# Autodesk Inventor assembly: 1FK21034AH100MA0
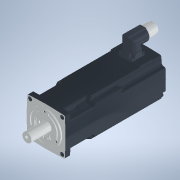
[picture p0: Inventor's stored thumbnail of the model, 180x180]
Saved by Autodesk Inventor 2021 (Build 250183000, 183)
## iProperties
Category: PARTsolutions
Created: 2026-06
Part Number: 1FK21034AH100MA0
Catalog Web Link: www.3dfindit.com
Description: 1FK21034AH100MA0-Servo synchronous motor
Document SubType Name: Assembly
Designer: psAdmin
Mass: 351.74 g
Surface Area: 934.015 cm^2
Volume: 351.74 cm^3
Density: 1 g/cm^3
Title: 1FK21034AH100MA0
Author: Cadenas PARTsolutions
Comments: Servo synchronous motor
PSOL_IDENT_0: {$CADENAS_DATA/23d-libs/siemens_ag/_cat_/39/97/1fk21034ah100ma0.prj},193 {STYP=ASS},{VTYP=3D},{NB=1F
PSOL_IDENT_1: K21034AH100MA0},{LINA=1FK21034AH100MA0},{NN=1FK21034AH100MA0},{DATE=19.08.2025 14:00:33},{GEOMDATE=3
PSOL_IDENT_2: 0.07.2025 02:02:21},{VERSION=},{LINEID=10},{WBVAR=},{WBNUMERIC=}  {NB=1FK21034AH100MA0},{LINA=1FK210
PSOL_IDENT_3: 34AH100MA0},{KT=DUMMY},{PREVIEW=../../../_pool_/d3/78/p_d211_xx_00934j.png},{DESCSHORT=SIMOTICS S-1F
PSOL_IDENT_4: K2 HD, SINAMICS S210 3AC 400V-480V, 1.01 Nm, 4500 rpm},{DESCLONG=SIMOTICS S-1FK2 HD servo motor M0=1
PSOL_IDENT_5: .27 Nm; PN = 0.48 kW at nN=4500 rpm (380-480 V); PN = 0.3 kW at nN=2500 rpm (200-240 V); with holdin
PSOL_IDENT_6: g brake; degree of protection IP64; cylindrical shaft D14 x 30 mm; absolute encoder 22-bit + 12-bit
PSOL_IDENT_7: multiturn (encoder AM22DQC); with OCC interface; plug size M17, rotatable; SIMOTICS S-1FK2 servomoto
PSOL_IDENT_8: rfor a wide range of uses in industrial environments. SIMOTICS S‑1FK2 servomotors are compact synchr
PSOL_IDENT_9: onous motors with a high dynamic performance that set themselves apart as a result of their high pow
PSOL_IDENT_10: er density, degree of protection and overload capability. The motors are available in two variants:
PSOL_IDENT_11: as High Dynamic variant (highest dynamic performance as a result of the low intrinsic moment of iner
PSOL_IDENT_12: tia for applications demanding a high dynamic performance with low moved masses) - and as Compact va
PSOL_IDENT_13: riant (precise and stable closed-loop control for medium up to large moved masses as a result of a m
PSOL_IDENT_14: edium intrinsic moment of inertia). SIMOTICSS‑1FK2 servomotors fully exploit their strengths in a sy
PSOL_IDENT_15: stem with the SINAMICSS210 frequency converter and simple connection using the one cable connection
PSOL_IDENT_16: (OCC). Advantages include the short control and positioning times, fast and precise correction of di
PSOL_IDENT_17: sturbing quantities as well as stable control with a high dynamic performance. The servo motors can
PSOL_IDENT_18: be configured to address a wide range of requirements. For example with and without holding brake, I
PSOL_IDENT_19: P64 or IP65 degree of protection, singleturn or multiturn absolute encoders - to name just a few. Fu
PSOL_IDENT_20: rther, the servomotors are available in different shaft heights extending from 20 to 100. A shaft se
PSOL_IDENT_21: aling ring is available to achieve an IP65 degree of protection and for subsequent mounting at the m
PSOL_IDENT_22: otor or as spare part. SIMOTICS - the optimum motor for each and every motion control application.},
PSOL_IDENT_23: {INTNO=195125454019},{SUPPLIERALTNO=1FK2103-4AH10-0MA0},{MANUID=1FK21034AH100MA0},{MANUNAME=Siemens}
PSOL_IDENT_24: ,{MANUTYPEDESC=SYNCHRONOUS MOTOR 1FK2 HD 1,27 NM},{AAU732=SIMOTICS},{AAO057=S-1FK2},{AAU734=SIMOTICS
PSOL_IDENT_25: S-1FK2 HD servo motor M0=1.27 Nm; PN = 0.48 kW at nN=4500 rpm (380-480 V); PN = 0.3 kW at nN=2500 r
PSOL_IDENT_26: pm (200-240 V); with holding brake; degree of protection IP64; cylindrical shaft D14 x 30 mm; absolu
PSOL_IDENT_27: te encoder 22-bit + 12-bit multiturn (encoder AM22DQC); with OCC interface; plug size M17, rotatable
PSOL_IDENT_28: ;},{AAW338=SYNCHRONOUS MOTOR 1FK2 HD 1,27 NM},{AAO742=SIMOTICS},{AAO663=4034106444921},{NOCUPEROU=1}
PSOL_IDENT_29: ,{PRICEQUANTITY=1},{QUANTITYMIN=1},{QUANTITYINT=1},{CTN=85015100},{COO=RO},{AAO676=1FK2103-4AH10-0MA
PSOL_IDENT_30: 0},{AAO677=Siemens AG},{ORDERUNIT=C62},{CONTENTUNIT=C62}
NB: 1FK21034AH100MA0
NN: 1FK21034AH100MA0
NT: Servo synchronous motor
NBSYN: $MANUID.
LINA: 1FK21034AH100MA0
CATALOG: SIEMENS
PREVIEW: ../../../_pool_/d3/78/p_d211_xx_00934j.png
DESCSHORT: SIMOTICS S-1FK2 HD, SINAMICS S210 3AC 400V-480V, 1.01 Nm, 4500 rpm
DESCLONG: SIMOTICS S-1FK2 HD servo motor M0=1.27 Nm; PN = 0.48 kW at nN=4500 rpm (380-480 V); PN = 0.3 kW at nN=2500 rpm (200-240 V); with holding brake; degree of protec
INTNO: 195125454019
SUPPLIERALTNO: 1FK2103-4AH10-0MA0
MANUID: 1FK21034AH100MA0
MANUNAME: Siemens
MANUTYPEDESC: SYNCHRONOUS MOTOR 1FK2 HD 1,27 NM
AAU732: SIMOTICS
AAO057: S-1FK2
AAU734: SIMOTICS S-1FK2 HD servo motor M0=1.27 Nm; PN = 0.48 kW at nN=4500 rpm (380-480 V); PN = 0.3 kW at nN=2500 rpm (200-240 V); with holding brake; degree of protec
AAW338: SYNCHRONOUS MOTOR 1FK2 HD 1,27 NM
AAO742: SIMOTICS
AAO663: 4034106444921.0
NOCUPEROU: 1
PRICEQUANTITY: 1
QUANTITYMIN: 1
QUANTITYINT: 1
CTN: 85015100
COO: RO
ARTICLENO: 1FK21034AH100MA0
BOMINFO: 1FK21034AH100MA0
CREATOR: CADENAS GmbH
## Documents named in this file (25)
- e:\temp\worker_COMMON_19\temp\tmp_8776_4_eR9rf\format_0\1FK21034AH100MA0.iam
- e:\temp\worker_COMMON_19\temp\tmp_8776_4_eR9rf\format_0\1FK21034AH100MA0_PART1.ipt
- e:\temp\worker_COMMON_19\temp\tmp_8776_4_eR9rf\format_0\1FK21034AH100MA0_PART2.ipt
- e:\temp\worker_COMMON_19\temp\tmp_8776_4_eR9rf\format_0\1FK21034AH100MA0_PART3.ipt
- e:\temp\worker_COMMON_19\temp\tmp_8776_4_eR9rf\format_0\1FK21034AH100MA0_PART4.ipt
- e:\temp\worker_COMMON_19\temp\tmp_8776_4_eR9rf\format_0\1FK21034AH100MA0_PART5.ipt
- e:\temp\worker_COMMON_19\temp\tmp_8776_4_eR9rf\format_0\1FK21034AH100MA0_PART6.ipt
- e:\temp\worker_COMMON_19\temp\tmp_8776_4_eR9rf\format_0\1FK21034AH100MA0_PART7.ipt
- e:\temp\worker_COMMON_19\temp\tmp_8776_4_eR9rf\format_0\1FK21034AH100MA0_PART8.ipt
- e:\temp\worker_COMMON_19\temp\tmp_8776_4_eR9rf\format_0\1FK21034AH100MA0_PART9.ipt
- e:\temp\worker_COMMON_19\temp\tmp_8776_4_eR9rf\format_0\1FK21034AH100MA0_PART10.ipt
- e:\temp\worker_COMMON_19\temp\tmp_8776_4_eR9rf\format_0\1FK21034AH100MA0_PART11.ipt
- e:\temp\worker_COMMON_19\temp\tmp_8776_4_eR9rf\format_0\1FK21034AH100MA0_PART12.ipt
- e:\temp\worker_COMMON_19\temp\tmp_8776_4_eR9rf\format_0\1FK21034AH100MA0_PART13.ipt
- e:\temp\worker_COMMON_19\temp\tmp_8776_4_eR9rf\format_0\1FK21034AH100MA0_PART14.ipt
- e:\temp\worker_COMMON_19\temp\tmp_8776_4_eR9rf\format_0\1FK21034AH100MA0_PART15.ipt
- e:\temp\worker_COMMON_19\temp\tmp_8776_4_eR9rf\format_0\1FK21034AH100MA0_PART16.ipt
- e:\temp\worker_COMMON_19\temp\tmp_8776_4_eR9rf\format_0\1FK21034AH100MA0_PART17.ipt
- e:\temp\worker_COMMON_19\temp\tmp_8776_4_eR9rf\format_0\1FK21034AH100MA0_PART18.ipt
- e:\temp\worker_COMMON_19\temp\tmp_8776_4_eR9rf\format_0\1FK21034AH100MA0_PART19.ipt
- e:\temp\worker_COMMON_19\temp\tmp_8776_4_eR9rf\format_0\1FK21034AH100MA0_PART20.ipt
- e:\temp\worker_COMMON_19\temp\tmp_8776_4_eR9rf\format_0\1FK21034AH100MA0_PART21.ipt
- e:\temp\worker_COMMON_19\temp\tmp_8776_4_eR9rf\format_0\1FK21034AH100MA0_PART22.ipt
- e:\temp\worker_COMMON_19\temp\tmp_8776_4_eR9rf\format_0\1FK21034AH100MA0_PART23.ipt
- e:\temp\worker_COMMON_19\temp\tmp_8776_4_eR9rf\format_0\1FK21034AH100MA0_PART24.ipt
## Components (24 placed, 24 different names)
1. 1FK21034AH100MA0_PART1:1
2. 1FK21034AH100MA0_PART2:1
3. 1FK21034AH100MA0_PART3:1
4. 1FK21034AH100MA0_PART4:1
5. 1FK21034AH100MA0_PART5:1
6. 1FK21034AH100MA0_PART6:1
7. 1FK21034AH100MA0_PART7:1
8. 1FK21034AH100MA0_PART8:1
9. 1FK21034AH100MA0_PART9:1
10. 1FK21034AH100MA0_PART10:1
11. 1FK21034AH100MA0_PART11:1
12. 1FK21034AH100MA0_PART12:1
13. 1FK21034AH100MA0_PART13:1
14. 1FK21034AH100MA0_PART14:1
15. 1FK21034AH100MA0_PART15:1
16. 1FK21034AH100MA0_PART16:1
17. 1FK21034AH100MA0_PART17:1
18. 1FK21034AH100MA0_PART18:1
19. 1FK21034AH100MA0_PART19:1
20. 1FK21034AH100MA0_PART20:1
21. 1FK21034AH100MA0_PART21:1
22. 1FK21034AH100MA0_PART22:1
23. 1FK21034AH100MA0_PART23:1
24. 1FK21034AH100MA0_PART24:1
